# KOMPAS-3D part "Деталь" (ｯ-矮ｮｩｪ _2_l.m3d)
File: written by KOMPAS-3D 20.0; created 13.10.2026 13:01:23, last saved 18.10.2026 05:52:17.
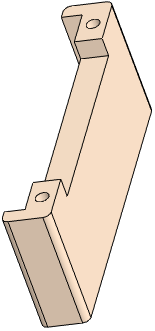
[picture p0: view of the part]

Document properties: Полное имя файла: D:\myProjects\Progect_esp32\box_compas\корпус\п-стойка_2_l.m3d

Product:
- Part/product: Деталь
    Масса: 0.0248378

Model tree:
1. Эскиз:1
2. Элемент выдавливания:1
     Расстояние 1 = 18.5
3. Эскиз:4  (with: Элемент выдавливания:1)
4. Элемент выдавливания:5
     Расстояние 2 = 18.5
5. Массив по сетке:2  (with: Элемент выдавливания:5, Эскиз:4)  (2 pattern instances)
     Шаг 1 = 10; Угол раствора = -90; Шаг 2 = 37
6. Эскиз:5  (with: Элемент выдавливания:1)
7. Элемент выдавливания:6
     Расстояние 2 = 5
8. Эскиз:6  (with: Элемент выдавливания:1)
9. Элемент выдавливания:7
     Расстояние 2 = 44
10. Элемент выдавливания:13  (with: Элемент выдавливания:1)
     Расстояние 1 = 1
11. Элемент выдавливания:14  (with: Элемент выдавливания:1)
     Расстояние 1 = 1
12. Эскиз:11  (with: Элемент выдавливания:1, Элемент выдавливания:13, Элемент выдавливания:14)
13. Элемент выдавливания:15
     Расстояние 2 = 3
14. Элемент выдавливания:16  (with: Элемент выдавливания:1)
     Расстояние 2 = 1
15. Элемент выдавливания:17  (with: Элемент выдавливания:1)
     Расстояние 1 = 1
16. Скругление:5  (with: Элемент выдавливания:16, Элемент выдавливания:17)
     Радиус = 1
